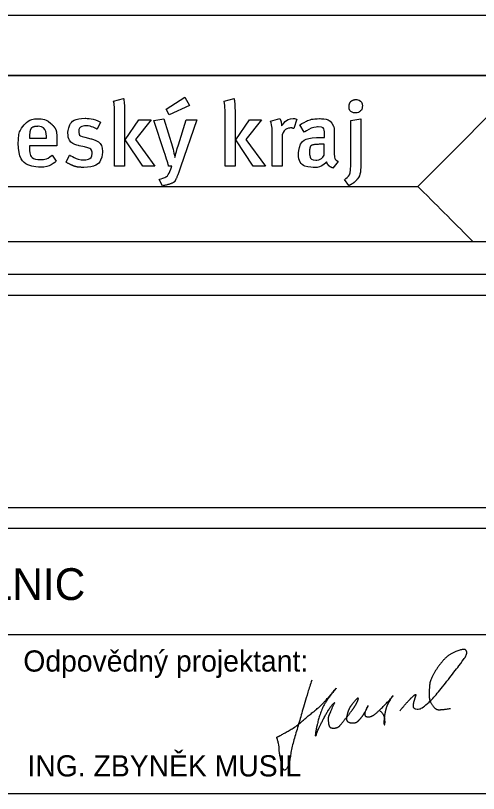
# Model space of a CAD drawing. Extents: x 2039 to 2249, y 760 to 1057.
# Drawn here: x 2099.4 to 2143.1, y 834.4 to 907.9 of the extents above; entities that cross this region are included whole.
import ezdxf

# ---------------------------------------------------------------- set-up
doc = ezdxf.new("R2010")
doc.units = 0
doc.layers.add('106_PRIKOP', color=7, linetype='Continuous')
doc.layers.add('120_ZPEVNENI', color=7, linetype='Continuous')

msp = doc.modelspace()

# ---------------------------------------------------------------- linework, layer by layer
at = {"layer": '106_PRIKOP'}
for points in [[(2135.715, 842.232), (2136.252, 842.892), (2136.852, 843.519), (2137.299, 843.909), (2137.089, 843.309), (2136.969, 842.862), (2136.969, 842.532), (2137.299, 842.382), (2137.809, 842.442), (2139.093, 843.639), (2141.577, 846.843), (2142.087, 847.59), (2141.997, 848.01), (2141.607, 848.07), (2140.29, 847.56), (2139.243, 846.333), (2138.526, 845.016), (2138.496, 843.999), (2138.496, 843.189), (2139.066, 842.382), (2139.603, 842.322), (2140.5, 842.472)], [(2127.396, 845.136), (2126.769, 843.189), (2126.169, 841.005), (2125.512, 838.878), (2125.302, 837.381), (2125.032, 836.754), (2124.795, 836.604), (2124.675, 836.754), (2124.555, 837.231), (2124.315, 838.371), (2124.345, 838.818), (2124.105, 839.748), (2124.045, 839.718), (2124.825, 840.135), (2125.932, 840.765), (2126.859, 841.602), (2128.086, 842.562), (2128.803, 843.309), (2129.7, 844.389), (2129.7, 844.359), (2128.533, 842.862), (2128.146, 841.812), (2127.906, 840.975), (2127.696, 839.868), (2127.816, 839.868), (2127.876, 840.225), (2128.233, 840.945), (2128.833, 842.112), (2129.37, 842.892), (2129.61, 843.039), (2129.49, 842.922), (2129.163, 842.142), (2128.953, 841.692), (2128.953, 841.245), (2129.043, 840.705), (2129.4, 840.585), (2129.91, 840.675), (2130.21, 841.035), (2131.317, 842.412), (2131.704, 843.069), (2131.794, 843.309), (2131.824, 843.429), (2131.674, 843.429), (2131.257, 842.922), (2130.867, 842.382), (2130.597, 841.335), (2131.017, 841.095), (2131.554, 841.095), (2131.914, 841.395), (2132.334, 841.932), (2132.841, 842.922), (2132.514, 842.412), (2132.334, 841.692), (2133.021, 841.662), (2133.591, 842.082), (2135.115, 843.639), (2135.055, 843.699), (2134.845, 843.369), (2134.488, 842.742), (2134.338, 842.172), (2134.218, 841.452), (2134.218, 840.855), (2134.338, 841.005), (2134.278, 841.872), (2133.828, 842.262)]]:
    msp.add_open_spline(points, degree=2, dxfattribs=at)
at = {"layer": '120_ZPEVNENI'}
for p, q in [((2233.65, 907.867), (2053.65, 907.867)), ((2108.678, 899.794), (2109.627, 900.027)), ((2119.113, 899.794), (2120.062, 900.027)), ((2123.507, 897.913), (2124.379, 898.136)), ((2125.992, 898.077), (2125.699, 897.196)), ((2107.433, 897.792), (2107.123, 897.135)), ((2126.695, 896.859), (2126.271, 897.542)), ((2100.732, 896.281), (2102.345, 896.281)), ((2105.974, 896.377), (2106.52, 896.237)), ((2129.525, 896.341), (2129.507, 895.09)), ((2105.94, 895.47), (2105.413, 895.582)), ((2128.569, 894.676), (2128.586, 895.712)), ((2102.89, 894.702), (2103.261, 894.124)), ((2104.189, 894.02), (2104.524, 894.702)), ((2114.475, 894.477), (2114.475, 894.486)), ((2114.173, 893.658), (2113.871, 893.658)), ((2129.888, 894.08), (2129.395, 893.476)), ((2113.302, 891.794), (2112.99, 892.406)), ((2130.895, 891.828), (2130.488, 892.38)), ((2053.65, 883.446), (2233.65, 883.446)), ((2053.65, 849.446), (2233.65, 849.446))]:
    msp.add_line(p, q, dxfattribs=at)
for points in [[(2137.41, 891.748), (2147.871, 902.209), (2058.95, 902.209), (2058.95, 891.748), (2137.41, 891.748)], [(2115.837, 899.371), (2113.939, 898.491), (2113.645, 899.034), (2115.405, 900.174), (2115.837, 899.371)], [(2109.713, 898.87), (2109.713, 893.658), (2108.773, 893.658), (2108.773, 898.741)], [(2120.148, 898.87), (2120.148, 893.658), (2119.208, 893.658), (2119.208, 898.741)], [(2111.431, 893.658), (2109.783, 896.126), (2111.076, 898.024), (2112.225, 898.024), (2110.732, 896.178), (2112.579, 893.658), (2111.431, 893.658)], [(2113.455, 895.013), (2112.464, 897.955), (2113.43, 898.12), (2114.234, 895.461)], [(2114.802, 895.66), (2115.525, 898.024), (2116.546, 898.024), (2115.001, 893.563)], [(2121.866, 893.658), (2120.219, 896.126), (2121.512, 898.024), (2122.661, 898.024), (2121.167, 896.178), (2123.015, 893.658), (2121.866, 893.658)], [(2131.075, 893.752), (2131.075, 897.955), (2132.034, 898.129), (2132.034, 893.761)], [(2124.612, 896.609), (2124.612, 893.658), (2123.661, 893.658), (2123.661, 896.738)], [(2128.31, 896.359), (2128.602, 896.359), (2128.602, 896.592)], [(2103.329, 895.781), (2103.329, 895.582), (2100.724, 895.582), (2100.724, 895.513)]]:
    msp.add_lwpolyline(points, dxfattribs=at)
for points in [[(2058.95, 902.209), (2147.871, 902.209), (2147.871, 886.517), (2058.95, 886.517)], [(2053.65, 861.446), (2233.65, 861.446), (2233.65, 881.446), (2053.65, 881.446)], [(2053.65, 834.446), (2233.65, 834.446), (2233.65, 859.446), (2053.65, 859.446)]]:
    msp.add_lwpolyline(points, close=True, dxfattribs=at)
for points, degree in [([(2108.773, 898.741), (2108.773, 898.741), (2108.773, 899.163), (2108.747, 899.457), (2108.678, 899.794)], 3), ([(2109.627, 900.027), (2109.627, 900.027), (2109.678, 899.75), (2109.713, 899.328), (2109.713, 898.87)], 3), ([(2119.208, 898.741), (2119.208, 898.741), (2119.208, 899.163), (2119.183, 899.457), (2119.113, 899.794)], 3), ([(2120.062, 900.027), (2120.062, 900.027), (2120.116, 899.75), (2120.148, 899.328), (2120.148, 898.87)], 3), ([(2130.919, 899.302), (2130.919, 899.302), (2130.919, 899.388), (2130.936, 899.466), (2130.973, 899.544)], 3), ([(2130.973, 899.544), (2131.042, 899.716), (2131.188, 899.854), (2131.36, 899.906)], 2), ([(2131.36, 899.906), (2131.36, 899.906), (2131.422, 899.932), (2131.481, 899.941), (2131.552, 899.941)], 3), ([(2131.552, 899.941), (2131.552, 899.941), (2131.896, 899.941), (2132.179, 899.655), (2132.179, 899.319)], 3), ([(2131.544, 898.671), (2131.544, 898.671), (2131.196, 898.671), (2130.919, 898.948), (2130.919, 899.302)], 3), ([(2131.912, 898.792), (2131.912, 898.792), (2131.81, 898.715), (2131.681, 898.671), (2131.544, 898.671)], 3), ([(2132.179, 899.319), (2132.179, 899.319), (2132.179, 899.096), (2132.077, 898.905), (2131.912, 898.792)], 3), ([(2100.223, 897.542), (2100.223, 897.542), (2100.576, 897.947), (2101.009, 898.129), (2101.561, 898.129)], 3), ([(2101.561, 898.129), (2101.561, 898.129), (2101.992, 898.129), (2102.388, 898.016), (2102.76, 897.68)], 3), ([(2104.368, 896.782), (2104.368, 896.782), (2104.368, 897.601), (2105.026, 898.171), (2105.991, 898.171)], 3), ([(2105.991, 898.171), (2105.991, 898.171), (2106.587, 898.171), (2107.064, 897.99), (2107.433, 897.792)], 3), ([(2124.379, 898.136), (2124.379, 898.136), (2124.483, 897.939), (2124.543, 897.688), (2124.543, 897.447)], 3), ([(2124.543, 897.447), (2124.543, 897.447), (2124.888, 897.921), (2125.232, 898.146), (2125.656, 898.146)], 3), ([(2125.656, 898.146), (2125.656, 898.146), (2125.793, 898.146), (2125.88, 898.129), (2125.992, 898.077)], 3), ([(2126.271, 897.542), (2126.271, 897.542), (2126.927, 897.955), (2127.472, 898.136), (2128.127, 898.136)], 3), ([(2128.127, 898.136), (2128.127, 898.136), (2128.807, 898.136), (2129.267, 897.886), (2129.457, 897.412)], 3), ([(2099.678, 895.833), (2099.678, 895.833), (2099.678, 896.601), (2099.844, 897.11), (2100.223, 897.542)], 3), ([(2101.561, 897.412), (2101.026, 897.412), (2100.732, 896.99), (2100.732, 896.281)], 2), ([(2102.345, 896.281), (2102.345, 896.281), (2102.345, 896.99), (2102.036, 897.412), (2101.561, 897.412)], 3), ([(2102.76, 897.68), (2103.14, 897.334), (2103.329, 896.799), (2103.329, 895.781)], 2), ([(2106.052, 897.455), (2106.052, 897.455), (2105.646, 897.455), (2105.387, 897.231), (2105.387, 896.894)], 3), ([(2107.123, 897.135), (2107.123, 897.135), (2106.717, 897.352), (2106.397, 897.455), (2106.052, 897.455)], 3), ([(2123.661, 896.738), (2123.661, 896.738), (2123.661, 897.291), (2123.603, 897.645), (2123.507, 897.913)], 3), ([(2125.431, 897.256), (2125.431, 897.256), (2125.036, 897.256), (2124.699, 896.963), (2124.612, 896.609)], 3), ([(2125.699, 897.196), (2125.604, 897.231), (2125.533, 897.256), (2125.431, 897.256)], 2), ([(2127.998, 897.36), (2127.998, 897.36), (2127.369, 897.36), (2126.695, 896.859), (2126.695, 896.859)], 3), ([(2128.602, 896.592), (2128.602, 896.592), (2128.602, 897.093), (2128.515, 897.36), (2127.998, 897.36)], 3), ([(2129.457, 897.412), (2129.457, 897.412), (2129.534, 897.222), (2129.534, 896.99), (2129.525, 896.341)], 3), ([(2105.413, 895.582), (2105.413, 895.582), (2104.758, 895.72), (2104.368, 896.169), (2104.368, 896.782)], 3), ([(2105.387, 896.894), (2105.387, 896.894), (2105.387, 896.627), (2105.535, 896.489), (2105.974, 896.377)], 3), ([(2101.689, 893.546), (2101.689, 893.546), (2100.454, 893.546), (2099.678, 894.434), (2099.678, 895.833)], 3), ([(2106.52, 896.237), (2106.52, 896.237), (2107.399, 896.014), (2107.632, 895.53), (2107.632, 895.022)], 3), ([(2126.15, 894.84), (2126.15, 894.84), (2126.15, 895.85), (2126.91, 896.359), (2128.31, 896.359)], 3), ([(2100.724, 895.513), (2100.724, 895.513), (2100.724, 894.909), (2100.947, 894.271), (2101.801, 894.271)], 3), ([(2107.632, 895.022), (2107.632, 895.022), (2107.632, 894.14), (2106.915, 893.536), (2105.862, 893.536)], 3), ([(2106.646, 894.857), (2106.646, 894.857), (2106.646, 895.194), (2106.433, 895.366), (2105.94, 895.47)], 3), ([(2113.871, 893.658), (2113.871, 893.658), (2113.749, 894.149), (2113.586, 894.624), (2113.455, 895.013)], 3), ([(2114.234, 895.461), (2114.234, 895.461), (2114.31, 895.194), (2114.475, 894.477), (2114.475, 894.477)], 3), ([(2114.475, 894.486), (2114.475, 894.486), (2114.491, 894.555), (2114.646, 895.159), (2114.802, 895.66)], 3), ([(2128.412, 895.72), (2127.464, 895.72), (2127.178, 895.444), (2127.178, 894.892)], 2), ([(2128.586, 895.712), (2128.586, 895.712), (2128.586, 895.712), (2128.482, 895.72), (2128.412, 895.72)], 3), ([(2129.507, 895.09), (2129.507, 895.09), (2129.507, 894.874), (2129.507, 894.711), (2129.534, 894.581)], 3), ([(2101.801, 894.271), (2101.801, 894.271), (2102.207, 894.271), (2102.562, 894.417), (2102.89, 894.702)], 3), ([(2104.524, 894.702), (2104.524, 894.702), (2104.912, 894.477), (2105.449, 894.244), (2105.94, 894.244)], 3), ([(2105.94, 894.244), (2105.94, 894.244), (2106.353, 894.244), (2106.646, 894.495), (2106.646, 894.857)], 3), ([(2127.601, 893.527), (2127.601, 893.527), (2126.6, 893.527), (2126.15, 894.08), (2126.15, 894.84)], 3), ([(2127.178, 894.892), (2127.178, 894.892), (2127.178, 894.477), (2127.403, 894.219), (2127.782, 894.219)], 3), ([(2127.782, 894.219), (2127.782, 894.219), (2128.082, 894.219), (2128.376, 894.4), (2128.569, 894.676)], 3), ([(2129.534, 894.581), (2129.534, 894.581), (2129.577, 894.356), (2129.681, 894.227), (2129.888, 894.08)], 3), ([(2103.261, 894.124), (2103.261, 894.124), (2102.804, 893.735), (2102.276, 893.546), (2101.689, 893.546)], 3), ([(2105.862, 893.536), (2105.327, 893.536), (2104.75, 893.709), (2104.189, 894.02)], 2), ([(2112.99, 892.406), (2112.99, 892.406), (2113.586, 892.57), (2113.921, 892.821), (2114.173, 893.658)], 3), ([(2115.001, 893.563), (2114.637, 892.511), (2114.328, 891.984), (2113.302, 891.794)], 2), ([(2128.8, 894.064), (2128.8, 894.064), (2128.447, 893.666), (2128.067, 893.527), (2127.601, 893.527)], 3), ([(2129.395, 893.476), (2129.129, 893.581), (2128.905, 893.788), (2128.8, 894.064)], 2), ([(2130.488, 892.38), (2130.488, 892.38), (2130.948, 892.699), (2131.075, 893.044), (2131.075, 893.752)], 3), ([(2132.034, 893.761), (2132.034, 893.761), (2132.034, 892.993), (2131.87, 892.648), (2131.714, 892.449)], 3), ([(2131.714, 892.449), (2131.515, 892.199), (2131.249, 891.984), (2130.895, 891.828)], 2), ([(2142.641, 886.517), (2142.641, 886.517), (2137.41, 891.748), (2137.41, 891.748), (2137.41, 891.748), (2137.41, 891.748), (2058.95, 891.748), (2058.95, 891.748), (2058.95, 891.748), (2058.95, 891.748), (2058.95, 886.517), (2058.95, 886.517), (2058.95, 886.517), (2058.95, 886.517), (2142.641, 886.517), (2142.641, 886.517)], 3)]:
    msp.add_open_spline(points, degree=degree, dxfattribs=at)

# ---------------------------------------------------------------- texts
for s, height, p in [('SILNIC A DÁLNIC', 3, (2073.462, 852.705)), ('Odpovědný projektant:', 2, (2100.15, 845.946))]:
    msp.add_text(s, height=height, dxfattribs=at).set_placement(p)
msp.add_text('ING. ZBYNĚK MUSIL', height=2, rotation=360, dxfattribs=at).set_placement((2100.545, 836.05))

doc.saveas('drawing.dxf')
